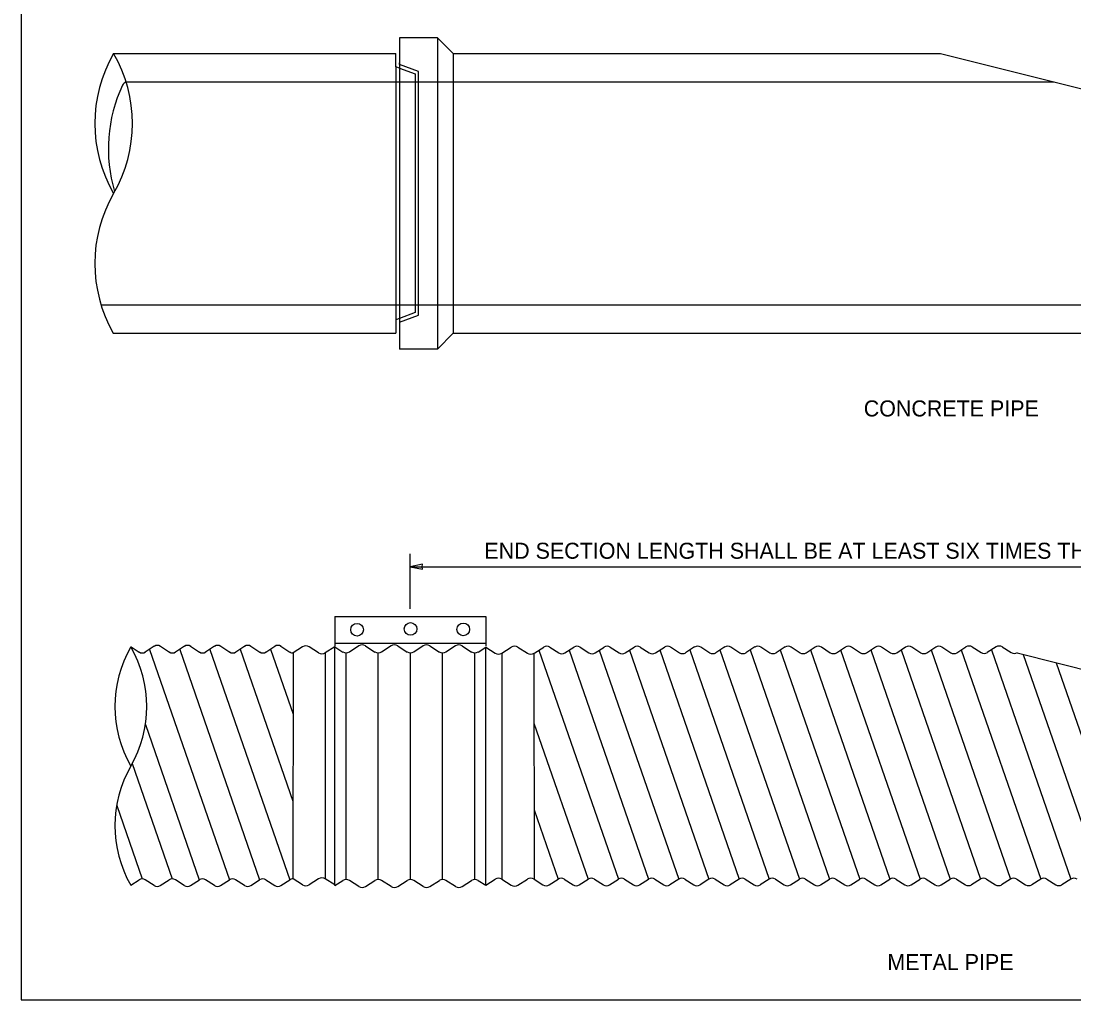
# Model space of a CAD drawing. Extents: x 99862 to 103680, y 99470 to 102076.
# Drawn here: x 99862 to 101176, y 100000 to 101221 of the extents above; entities that cross this region are included whole.
import ezdxf

# ---------------------------------------------------------------- set-up
doc = ezdxf.new("R2010")
doc.units = 0
for name, color, linetype in [('Default', 7, 'Continuous'), ('Level 1', 7, 'Continuous'), ('Level 15', 7, 'Continuous'), ('Level 18', 7, 'Continuous'), ('Level 20', 7, 'Continuous'), ('Level 6', 7, 'Continuous'), ('Level 60', 7, 'Continuous')]:
    doc.layers.add(name, color=color, linetype=linetype)

msp = doc.modelspace()

# ---------------------------------------------------------------- linework, layer by layer
at = {"layer": 'Default'}
msp.add_lwpolyline([(100347.3, 100539.8), (100363, 100536.7), (100362.3, 100539.8), (100363, 100542.9)], close=True, dxfattribs=at)
at = {"layer": 'Level 1'}
msp.add_lwpolyline([(99862, 99999.5), (103151, 99999.5), (103151, 102075.5), (99862, 102075.5)], close=True, dxfattribs=at)
at = {"layer": 'Level 15'}
for p, q in [((100347.3, 100487.4), (100347.3, 100555.8)), ((100347.3, 100539.8), (102014.8, 100539.8))]:
    msp.add_line(p, q, dxfattribs=at)
at = {"layer": 'Level 18'}
for p, q in [((100253.4, 100477.9), (100441.7, 100477.9)), ((100253.4, 100477.9), (100253.4, 100440.7)), ((100441.7, 100477.9), (100441.7, 100440.7)), ((100253.4, 100444.6), (100441.7, 100444.6)), ((100253.4, 100142.2), (100253.4, 100440)), ((100441.7, 100142.6), (100441.7, 100439.6))]:
    msp.add_line(p, q, dxfattribs=at)
for centre in [(100281.2, 100461.3), (100347.9, 100462.2), (100413.8, 100461.7)]:
    msp.add_circle(centre, 7.9, dxfattribs=at)
at = {"layer": 'Level 6'}
for p, q in [((100334.1, 101199.7), (100334.1, 100811.4)), ((100381.4, 101199.7), (100334.1, 101199.7)), ((100381.4, 101199.7), (100401, 101180.1)), ((100381.4, 101199.7), (100381.4, 100811.4)), ((99977.4, 101180.1), (100329.5, 101180.1)), ((100329.5, 101163.5), (100329.5, 101180.1)), ((100401, 101180.1), (101009, 101180.1)), ((100401, 101180.1), (100401, 100831.2)), ((101009, 101180.1), (102015.5, 100928.5)), ((100334.1, 101166.5), (100334.1, 101168.5)), ((100357.7, 101157.8), (100334.1, 101166.5)), ((100329.5, 101163.5), (100329.5, 100831.2)), ((100334.1, 101161.8), (100329.5, 101163.5)), ((100334.1, 101161.8), (100353.9, 101154.5)), ((100353.9, 101154.5), (100353.9, 100856.8)), ((100357.7, 101144.6), (100357.7, 101157.8)), ((99993, 101144.6), (101150.9, 101144.6)), ((100357.7, 100853.6), (100357.7, 101144.6)), ((99961.8, 100866.7), (102015.5, 100866.7)), ((100334.1, 100849.5), (100329.5, 100847.8)), ((100353.9, 100856.8), (100334.1, 100849.5)), ((100334.1, 100844.8), (100357.7, 100853.6)), ((99977.1, 100831.2), (100329.5, 100831.2)), ((100401.1, 100831.2), (100381.4, 100811.4)), ((100401, 100831.2), (102015.5, 100831.2)), ((100381.4, 100811.4), (100334.1, 100811.4)), ((99999.3, 100439.9), (100009.4, 100433.5)), ((100028.2, 100440.6), (100017, 100433.5)), ((100022.3, 100436.8), (100122, 100149.4)), ((100035.8, 100440.6), (100047, 100433.5)), ((100065.8, 100440.6), (100054.7, 100433.5)), ((100059.9, 100436.8), (100159.6, 100149.4)), ((100073.5, 100440.6), (100084.7, 100433.5)), ((100103.5, 100440.6), (100092.3, 100433.5)), ((100097.5, 100436.8), (100197.2, 100149.4)), ((100111.1, 100440.6), (100122.3, 100433.5)), ((100141.1, 100440.6), (100129.9, 100433.5)), ((100135.5, 100437), (100201.2, 100247.5)), ((100148.7, 100440.6), (100159.9, 100433.5)), ((100167.5, 100433.5), (100178.7, 100440.6)), ((100173.1, 100437), (100201.3, 100355.8)), ((100186.3, 100440.6), (100197.5, 100433.5)), ((100201.3, 100432.3), (100201.2, 100150.6)), ((100213.3, 100440), (100201.3, 100432.3)), ((100233.3, 100432.3), (100221.4, 100440)), ((100253.4, 100440), (100241.5, 100432.3)), ((100241.6, 100432.4), (100241.5, 100150.7)), ((100253.4, 100440), (100263.5, 100433.5)), ((100267.5, 100245.1), (100267.5, 100432.4)), ((100283.6, 100441.2), (100271.6, 100433.5)), ((100291.7, 100441.2), (100303.6, 100433.5)), ((100307.7, 100245.1), (100307.7, 100432.4)), ((100323.7, 100441.2), (100311.8, 100433.5)), ((100331.9, 100441.2), (100343.8, 100433.5)), ((100347.8, 100149.8), (100347.8, 100432.4)), ((100363.9, 100441.2), (100351.9, 100433.5)), ((100372, 100441.2), (100384, 100433.5)), ((100387.9, 100245.1), (100387.9, 100432.4)), ((100404, 100441.2), (100392.1, 100433.5)), ((100412.2, 100441.2), (100424.1, 100433.5)), ((100428.1, 100245.1), (100428.1, 100432.4)), ((100432.2, 100433.5), (100441.7, 100439.6)), ((100441.7, 100439.6), (100453.6, 100431.9)), ((100461.7, 100431.9), (100473.7, 100439.6)), ((100461.7, 100431.9), (100461.7, 100150.2)), ((100481.8, 100439.6), (100493.8, 100431.9)), ((100501.9, 100431.9), (100502, 100150.1)), ((100502.9, 100432.5), (100514.1, 100439.7)), ((100508.2, 100435.9), (100607.3, 100150.1)), ((100521.7, 100439.7), (100532.9, 100432.5)), ((100540.6, 100432.5), (100551.7, 100439.7)), ((100545.8, 100435.9), (100644.9, 100150.2)), ((100559.4, 100439.7), (100570.6, 100432.5)), ((100578.2, 100432.5), (100589.4, 100439.7)), ((100583.4, 100435.9), (100682.5, 100150.2)), ((100597, 100439.7), (100608.2, 100432.5)), ((100615.8, 100432.5), (100627, 100439.7)), ((100621, 100435.9), (100720.1, 100150.2)), ((100634.6, 100439.7), (100645.8, 100432.5)), ((100653.4, 100432.5), (100664.6, 100439.7)), ((100658.8, 100436), (100757.9, 100150.2)), ((100672.4, 100439.8), (100683.6, 100432.6)), ((100702.4, 100439.8), (100691.2, 100432.6)), ((100696.4, 100436), (100795.5, 100150.2)), ((100710, 100439.8), (100721.2, 100432.6)), ((100740, 100439.8), (100728.8, 100432.6)), ((100734, 100436), (100833.1, 100150.2)), ((100747.6, 100439.8), (100758.8, 100432.6)), ((100777.6, 100439.8), (100766.4, 100432.6)), ((100771.7, 100436), (100870.8, 100150.2)), ((100785.2, 100439.8), (100796.4, 100432.6)), ((100815.2, 100439.8), (100804, 100432.6)), ((100809.3, 100436), (100908.4, 100150.2)), ((100822.8, 100439.8), (100834, 100432.6)), ((100841.6, 100432.6), (100852.8, 100439.8)), ((100846.9, 100436), (100946, 100150.2)), ((100860.5, 100439.8), (100871.6, 100432.6)), ((100879.3, 100432.6), (100890.5, 100439.8)), ((100884.5, 100436), (100983.6, 100150.2)), ((100898.1, 100439.8), (100909.3, 100432.6)), ((100916.9, 100432.6), (100928.1, 100439.8)), ((100922.1, 100436), (101021.2, 100150.2)), ((100935.7, 100439.8), (100946.9, 100432.6)), ((100954.5, 100432.6), (100965.7, 100439.8)), ((100959.9, 100436.1), (101059, 100150.3)), ((100973.3, 100439.8), (100984.5, 100432.6)), ((100992.1, 100432.6), (101003.3, 100439.8)), ((100997.5, 100436.1), (101096.6, 100150.3)), ((101010.9, 100439.8), (101022.1, 100432.6)), ((101029.7, 100432.6), (101040.9, 100439.8)), ((101035.1, 100436.1), (101134.2, 100150.3)), ((101048.7, 100439.9), (101059.9, 100432.7)), ((101078.7, 100439.9), (101067.5, 100432.7)), ((101072.7, 100436.1), (101171.8, 100150.3)), ((101086.3, 100439.9), (101097.5, 100432.7)), ((101104.8, 100432.3), (102014.8, 100204.8)), ((101112.3, 100430.4), (101209.5, 100150.3)), ((101153.5, 100420.1), (101247.1, 100150.3)), ((100017.3, 100342.9), (100084.4, 100149.4)), ((100501.9, 100344.9), (100569.5, 100150.1)), ((100000.8, 100294.3), (100050.7, 100150.6)), ((99981.3, 100242.2), (100013.1, 100150.6)), ((100267.5, 100149.8), (100267.5, 100245.1)), ((100307.7, 100149.8), (100307.7, 100245.1)), ((100387.9, 100149.8), (100387.9, 100245.1)), ((100428.1, 100149.8), (100428.1, 100245.1)), ((100502, 100236.8), (100532, 100150.1)), ((99998.8, 100142.7), (100009.3, 100149.4)), ((100028.1, 100142.3), (100016.9, 100149.4)), ((100035.7, 100142.3), (100046.9, 100149.4)), ((100065.7, 100142.3), (100054.5, 100149.4)), ((100073.3, 100142.3), (100084.5, 100149.4)), ((100103.3, 100142.3), (100092.1, 100149.4)), ((100110.9, 100142.3), (100122.1, 100149.4)), ((100140.9, 100142.3), (100129.7, 100149.4)), ((100148.6, 100142.3), (100159.7, 100149.4)), ((100167.4, 100149.4), (100178.6, 100142.3)), ((100186.2, 100142.3), (100197.4, 100149.4)), ((100213.3, 100143), (100201.3, 100150.7)), ((100233.3, 100150.7), (100221.4, 100143)), ((100253.4, 100143), (100241.5, 100150.7)), ((100253.4, 100142.2), (100263.5, 100148.6)), ((100283.6, 100141), (100271.6, 100148.6)), ((100291.7, 100141), (100303.6, 100148.6)), ((100323.7, 100141), (100311.8, 100148.6)), ((100331.9, 100141), (100343.8, 100148.6)), ((100363.9, 100141), (100351.9, 100148.6)), ((100372, 100141), (100384, 100148.6)), ((100404, 100141), (100392.1, 100148.6)), ((100412.2, 100141), (100424.1, 100148.6)), ((100432.2, 100148.6), (100441.7, 100142.6)), ((100441.7, 100142.6), (100453.6, 100150.2)), ((100461.7, 100150.2), (100473.7, 100142.6)), ((100481.8, 100142.6), (100493.8, 100150.2)), ((100502, 100150.1), (100513.2, 100143)), ((100520.9, 100143), (100532, 100150.1)), ((100539.7, 100150.1), (100550.9, 100143)), ((100558.5, 100143), (100569.7, 100150.1)), ((100577.3, 100150.1), (100588.5, 100143)), ((100596.1, 100143), (100607.3, 100150.1)), ((100614.9, 100150.1), (100626.1, 100143)), ((100633.7, 100143), (100644.9, 100150.1)), ((100652.7, 100150.2), (100663.9, 100143.1)), ((100682.7, 100150.2), (100671.5, 100143.1)), ((100690.3, 100150.2), (100701.5, 100143.1)), ((100720.3, 100150.2), (100709.1, 100143.1)), ((100727.9, 100150.2), (100739.1, 100143.1)), ((100757.9, 100150.2), (100746.7, 100143.1)), ((100765.5, 100150.2), (100776.7, 100143.1)), ((100795.5, 100150.2), (100784.3, 100143.1)), ((100803.1, 100150.2), (100814.3, 100143.1)), ((100821.9, 100143.1), (100833.1, 100150.2)), ((100840.8, 100150.2), (100851.9, 100143.1)), ((100859.6, 100143.1), (100870.8, 100150.2)), ((100878.4, 100150.2), (100889.6, 100143.1)), ((100897.2, 100143.1), (100908.4, 100150.2)), ((100916, 100150.2), (100927.2, 100143.1)), ((100934.8, 100143.1), (100946, 100150.2)), ((100953.6, 100150.2), (100964.8, 100143.1)), ((100972.4, 100143.1), (100983.6, 100150.2)), ((100991.2, 100150.2), (101002.4, 100143.1)), ((101010, 100143.1), (101021.2, 100150.2)), ((101029, 100150.3), (101040.2, 100143.2)), ((101059, 100150.3), (101047.8, 100143.2)), ((101066.6, 100150.3), (101077.8, 100143.2)), ((101096.6, 100150.3), (101085.4, 100143.2)), ((101104.2, 100150.3), (101115.4, 100143.2)), ((101134.2, 100150.3), (101123, 100143.2)), ((101141.8, 100150.3), (101153, 100143.2)), ((101171.8, 100150.3), (101160.7, 100143.2))]:
    msp.add_line(p, q, dxfattribs=at)
for centre, radius, start, end in [((100128.7, 101092.7), 174.7, 150, 210), ((99826.2, 101092.7), 174.7, 330, 30), ((100157.3, 101061.4), 186.4, 154.8621, 196.6957), ((99998.2, 101134.7), 11.2, 117.7649, 148.6994), ((100128.7, 100918), 174.7, 150, 209.799), ((100287.6, 100434.9), 7.53, 56, 124), ((100327.8, 100434.9), 7.53, 56, 124), ((100367.9, 100434.9), 7.53, 56, 124), ((100408.1, 100434.9), 7.53, 56, 124), ((100127.9, 100365.5), 148.8, 150, 210), ((99870.2, 100365.5), 148.8, 330, 30), ((100013.2, 100439.4), 7.05, 236, 304), ((100032, 100434.7), 7.05, 56, 124), ((100050.8, 100439.4), 7.05, 236, 304), ((100069.7, 100434.7), 7.05, 56, 124), ((100088.5, 100439.4), 7.05, 236, 304), ((100107.3, 100434.7), 7.05, 56, 124), ((100126.1, 100439.4), 7.05, 236, 304), ((100144.9, 100434.7), 7.05, 56, 124), ((100163.7, 100439.4), 7.05, 236, 304), ((100182.5, 100434.7), 7.05, 56, 124), ((100201.3, 100439.4), 7.05, 236, 270), ((100217.3, 100433.7), 7.53, 56, 124), ((100237.4, 100438.7), 7.53, 236, 304), ((100267.6, 100439.9), 7.53, 236, 304), ((100307.7, 100439.9), 7.53, 236, 304), ((100347.9, 100439.9), 7.53, 236, 304), ((100388, 100439.9), 7.53, 236, 304), ((100428.2, 100439.9), 7.53, 236, 304), ((100457.7, 100438.3), 7.53, 236, 304), ((100477.8, 100433.2), 7.53, 56, 124), ((100497.8, 100438.3), 7.53, 236, 304), ((100499.1, 100438.4), 7.05, 294.4589, 304), ((100517.9, 100433.7), 7.05, 56, 124), ((100536.7, 100438.4), 7.05, 236, 304), ((100555.6, 100433.7), 7.05, 56, 124), ((100574.4, 100438.4), 7.05, 236, 304), ((100593.2, 100433.7), 7.05, 56, 124), ((100612, 100438.4), 7.05, 236, 304), ((100630.8, 100433.7), 7.05, 56, 124), ((100649.6, 100438.4), 7.05, 236, 304), ((100668.6, 100433.8), 7.05, 56, 124), ((100687.4, 100438.5), 7.05, 236, 304), ((100706.2, 100433.8), 7.05, 56, 124), ((100725, 100438.5), 7.05, 236, 304), ((100743.8, 100433.8), 7.05, 56, 124), ((100762.6, 100438.5), 7.05, 236, 304), ((100781.4, 100433.8), 7.05, 56, 124), ((100800.2, 100438.5), 7.05, 236, 304), ((100819, 100433.8), 7.05, 56, 124), ((100837.8, 100438.5), 7.05, 236, 304), ((100856.6, 100433.8), 7.05, 56, 124), ((100875.5, 100438.5), 7.05, 236, 304), ((100894.3, 100433.8), 7.05, 56, 124), ((100913.1, 100438.5), 7.05, 236, 304), ((100931.9, 100433.8), 7.05, 56, 124), ((100950.7, 100438.5), 7.05, 236, 304), ((100969.5, 100433.8), 7.05, 56, 124), ((100988.3, 100438.5), 7.05, 236, 304), ((101007.1, 100433.8), 7.05, 56, 124), ((101025.9, 100438.5), 7.05, 236, 304), ((101044.9, 100433.9), 7.05, 56, 124), ((101063.7, 100438.6), 7.05, 236, 304), ((101082.5, 100433.9), 7.05, 56, 124), ((101101.3, 100438.6), 7.05, 236, 304), ((100127.9, 100216.7), 148.8, 150, 209.7989), ((100013.1, 100143.5), 7.05, 56, 124), ((100031.9, 100148.2), 7.05, 236, 304), ((100050.7, 100143.5), 7.05, 56, 124), ((100069.5, 100148.2), 7.05, 236, 304), ((100088.3, 100143.5), 7.05, 56, 124), ((100107.1, 100148.2), 7.05, 236, 304), ((100125.9, 100143.5), 7.05, 56, 124), ((100144.7, 100148.2), 7.05, 236, 304), ((100163.6, 100143.5), 7.05, 56, 124), ((100182.4, 100148.2), 7.05, 236, 304), ((100201.2, 100143.5), 7.05, 90, 124), ((100217.3, 100149.3), 7.53, 236, 304), ((100237.4, 100144.3), 7.53, 56, 124), ((100267.6, 100142.3), 7.53, 56, 124), ((100287.6, 100147.3), 7.53, 236, 304), ((100307.7, 100142.3), 7.53, 56, 124), ((100327.8, 100147.3), 7.53, 236, 304), ((100347.9, 100142.3), 7.53, 56, 124), ((100367.9, 100147.3), 7.53, 236, 304), ((100388, 100142.3), 7.53, 56, 124), ((100408.1, 100147.3), 7.53, 236, 304), ((100428.2, 100142.3), 7.53, 56, 124), ((100457.7, 100143.9), 7.53, 56, 124), ((100477.8, 100148.9), 7.53, 236, 304), ((100497.8, 100143.9), 7.53, 56, 124), ((100517, 100148.9), 7.05, 236, 304), ((100535.9, 100144.2), 7.05, 56, 124), ((100554.7, 100148.9), 7.05, 236, 304), ((100573.5, 100144.2), 7.05, 56, 124), ((100592.3, 100148.9), 7.05, 236, 304), ((100611.1, 100144.2), 7.05, 56, 124), ((100629.9, 100148.9), 7.05, 236, 304), ((100648.9, 100144.3), 7.05, 56, 124), ((100667.7, 100149), 7.05, 236, 304), ((100686.5, 100144.3), 7.05, 56, 124), ((100705.3, 100149), 7.05, 236, 304), ((100724.1, 100144.3), 7.05, 56, 124), ((100742.9, 100149), 7.05, 236, 304), ((100761.7, 100144.3), 7.05, 56, 124), ((100780.5, 100149), 7.05, 236, 304), ((100799.3, 100144.3), 7.05, 56, 124), ((100818.1, 100149), 7.05, 236, 304), ((100836.9, 100144.3), 7.05, 56, 124), ((100855.8, 100149), 7.05, 236, 304), ((100874.6, 100144.3), 7.05, 56, 124), ((100893.4, 100149), 7.05, 236, 304), ((100912.2, 100144.3), 7.05, 56, 124), ((100931, 100149), 7.05, 236, 304), ((100949.8, 100144.3), 7.05, 56, 124), ((100968.6, 100149), 7.05, 236, 304), ((100987.4, 100144.3), 7.05, 56, 124), ((101006.2, 100149), 7.05, 236, 304), ((101025.2, 100144.4), 7.05, 56, 124), ((101044, 100149.1), 7.05, 236, 304), ((101062.8, 100144.4), 7.05, 56, 124), ((101081.6, 100149.1), 7.05, 236, 304), ((101100.4, 100144.4), 7.05, 56, 124), ((101119.2, 100149.1), 7.05, 236, 304), ((101138, 100144.4), 7.05, 56, 124), ((101156.8, 100149.1), 7.05, 236, 304), ((101175.7, 100144.4), 7.05, 56, 124)]:
    msp.add_arc(centre, radius, start, end, dxfattribs=at)
at = {"layer": 'Level 60'}
msp.add_line((99862, 99999.5), (99862, 99999.5), dxfattribs=at)

# ---------------------------------------------------------------- texts
at = {"layer": 'Level 20'}
for s, p in [('CONCRETE PIPE', (100913.4, 100727.3)), ('END SECTION LENGTH SHALL BE AT LEAST SIX TIMES THE DIAMETER OF THE PIPE (SEE', (100440.1, 100549.8)), ('METAL PIPE', (100942.8, 100036.7))]:
    msp.add_text(s, height=20, dxfattribs=at).set_placement(p)

doc.saveas('drawing.dxf')
